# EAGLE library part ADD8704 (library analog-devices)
16 V Quad Operational Amplifier Source: Ananlog Devices .. 780914713ADD8704_0.pdf
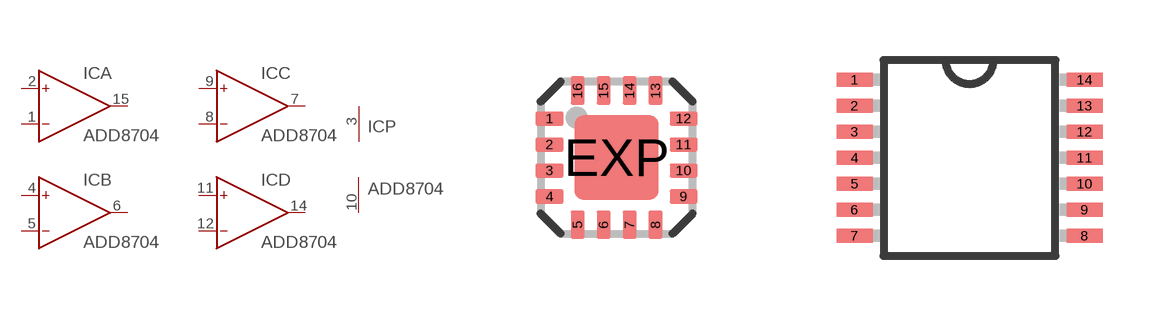
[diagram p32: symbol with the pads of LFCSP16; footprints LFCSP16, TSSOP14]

Designator prefix IC; gates A=OP B=OP C=OP D=OP P=PWR+-

## ADD8704CP (MF: ALTERA CORPORATION; MPN: ADD8704ACPZ-REEL7; OC_FARNELL: unknown; OC_NEWARK: 59K0961)  [LFCSP16]
1  A:IN-  in
2  A:IN+  in
3  P:V+  pwr
4  B:IN+  in
5  B:IN-  in
6  B:OUT  out
7  C:OUT  out
8  C:IN-  in
9  C:IN+  in
10  P:V-  pwr
11  D:IN+  in
12  D:IN-  in
14  D:OUT  out
15  A:OUT  out

## ADD8704RU (MF: ALTERA CORPORATION; MPN: ADD8704ARUZ-REEL; OC_FARNELL: unknown; OC_NEWARK: 59K0964)  [TSSOP14]
1  A:OUT  out
2  A:IN-  in
3  A:IN+  in
4  P:V+  pwr
5  B:IN+  in
6  B:IN-  in
7  B:OUT  out
8  C:OUT  out
9  C:IN-  in
10  C:IN+  in
11  P:V-  pwr
12  D:IN+  in
13  D:IN-  in
14  D:OUT  out

## Footprint LFCSP16 (pad centres in mm)
16-Terminal Leadless Frame Chip Scale Package [LFCSP] (CP) Source: Analog Devices .. 780914713ADD8704_0.pdf
smd 0.7 x 0.35: 1 -1.675,0.975; 2 -1.675,0.325; 3 -1.675,-0.325; 4 -1.675,-0.975; 9 1.675,-0.975; 10 1.675,-0.325; 11 1.675,0.325; 12 1.675,0.975
smd 0.35 x 0.7: 5 -0.975,-1.675; 6 -0.325,-1.675; 7 0.325,-1.675; 8 0.975,-1.675; 13 0.975,1.675; 14 0.325,1.675; 15 -0.325,1.675; 16 -0.975,1.675
smd 2.1 x 2.1: EXP 0,0

## Footprint TSSOP14 (pad centres in mm)
14-Lead Thin Shrink Small Outline Package [TSSOP] Source: Analog Devices .. 780914713ADD8704_0.pdf
smd 0.9 x 0.35: 1 -2.875,1.95; 2 -2.875,1.3; 3 -2.875,0.65; 4 -2.875,0; 5 -2.875,-0.65; 6 -2.875,-1.3; 7 -2.875,-1.95; 8 2.875,-1.95; 9 2.875,-1.3; 10 2.875,-0.65; 11 2.875,0; 12 2.875,0.65; 13 2.875,1.3; 14 2.875,1.95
